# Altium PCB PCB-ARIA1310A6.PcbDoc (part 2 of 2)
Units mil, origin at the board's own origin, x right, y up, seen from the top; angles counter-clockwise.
Board outline 6000 x 4000 mil, 2 copper layers (Top Layer, Bottom Layer); 128 components, 134 nets, 554 pads, 227 vias.
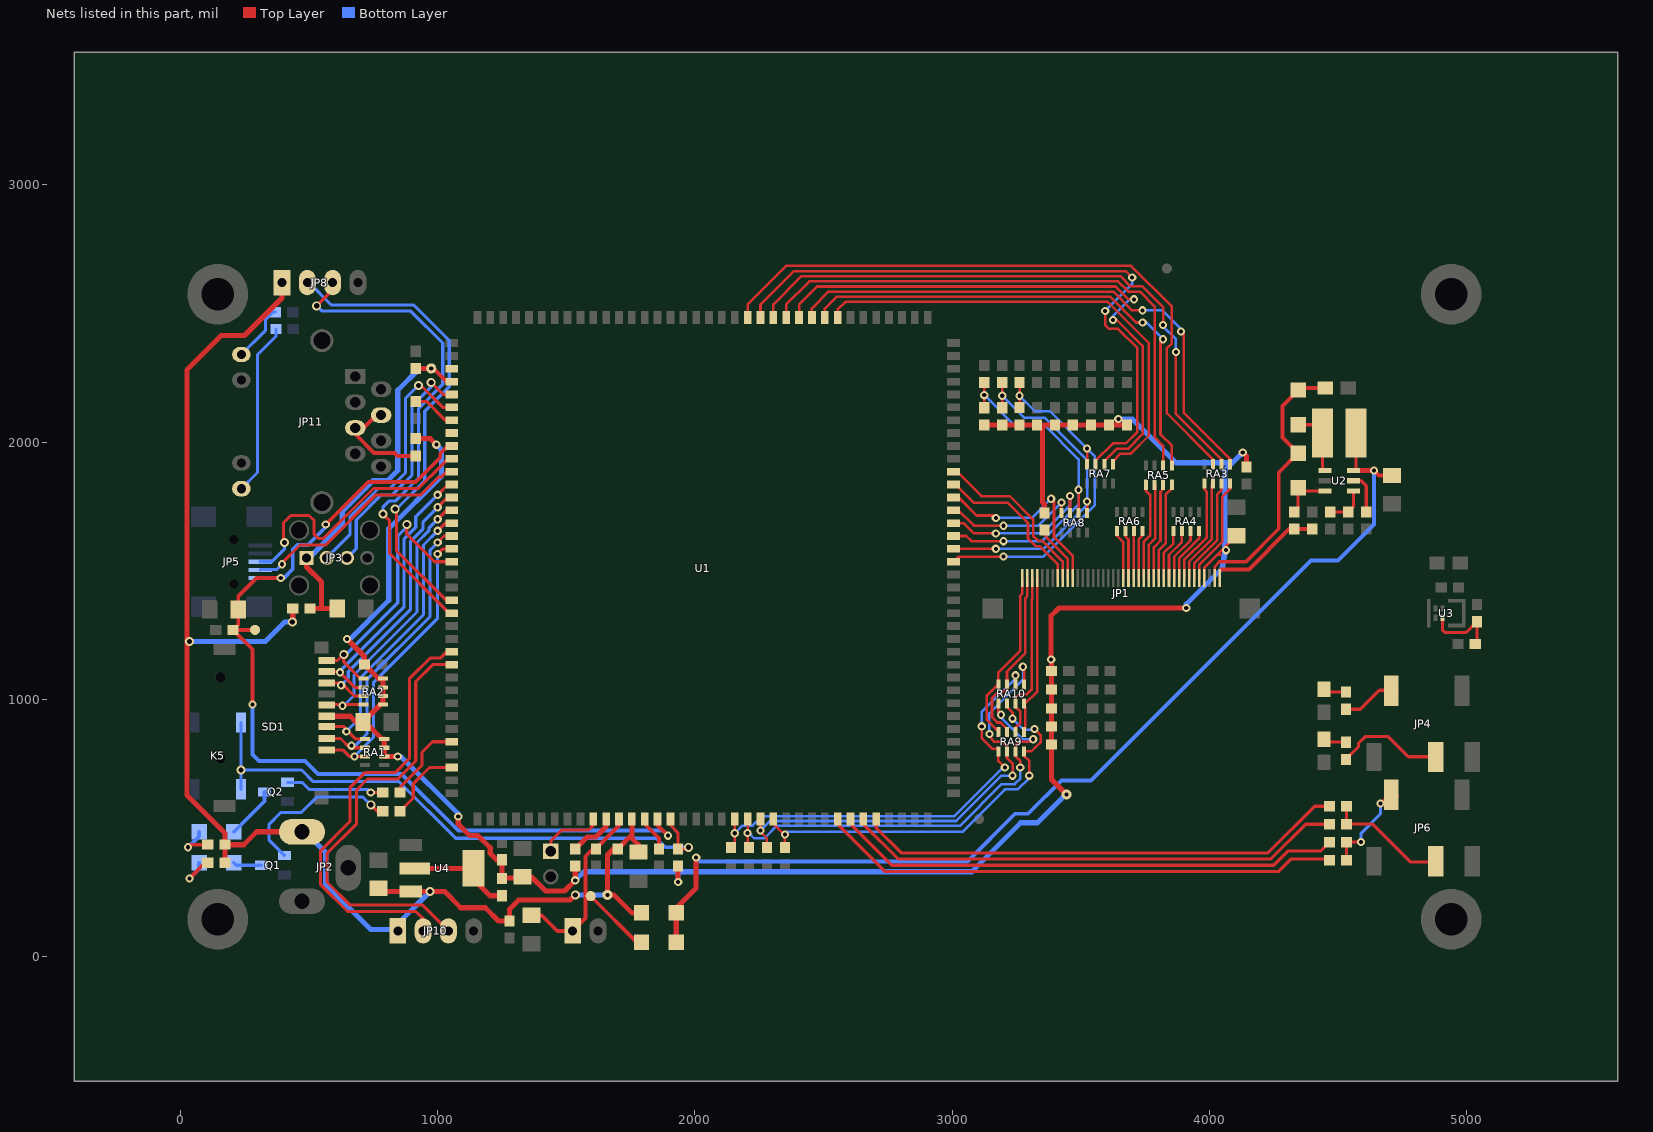
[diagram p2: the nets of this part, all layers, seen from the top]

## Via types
v1: diameter 32, hole 16, Top Layer to Bottom Layer, 208 vias
v2: diameter 35, hole 20, Top Layer to Bottom Layer, 19 vias

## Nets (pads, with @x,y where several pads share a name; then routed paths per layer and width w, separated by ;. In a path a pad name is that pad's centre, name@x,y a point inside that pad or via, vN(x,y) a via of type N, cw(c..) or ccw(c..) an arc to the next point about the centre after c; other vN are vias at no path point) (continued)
LCD_DATA11: R36.2 R47.1 RA7.5 U1.127 | length 1379.6
  Top Layer w10: U1.127@3005,1535 3025,1555 v1(3200,1555) ; R36.2@3262.48,2133.86 v1(3262.48,2180) R47.1@3262.48,2231.54 ; RA7.5@3524.8,1913.9 v1(3524.8,1975)
  Bottom Layer w10: v1(3200,1555) 3355,1555 3555,1755 3555,1944.8 v1(3524.8,1975) 3379.8,2120 3322.48,2120 v1(3262.48,2180)
LCD_DATA12: R35.2 R46.1 RA8.8 U1.128 | length 1342.4
  Top Layer w10: U1.128@3005,1585 v1(3170,1585) ; R35.2@3195,2133.46 v1(3195,2180) R46.1@3195,2231.54 ; v1(3524.8,1769.22) 3524.8,1724.29 RA8.8@3525.2,1723.9
  Bottom Layer w10: v1(3170,1585) 3355,1585 3524.8,1754.8 v1(3524.8,1769.22) 3524.8,1930.2 3360,2095 3280,2095 v1(3195,2180)
LCD_DATA13: R34.2 R45.1 RA8.7 U1.129 | length 1389.3
  Top Layer w10: U1.129@3005,1635 3055,1635 3075,1615 v1(3200,1615) ; R34.2@3125,2133.46 v1(3125,2182.5) R45.1@3125,2231.54 ; RA8.7@3491.73,1723.9 v1(3491.73,1815)
  Bottom Layer w10: v1(3125,2182.5) 3237.5,2070 3355,2070 3491.73,1933.27 3491.73,1756.93 3349.8,1615 v1(3200,1615)
LCD_DATA14: RA8.6 U1.130 | length 624.6
  Top Layer w10: U1.130@3010,1680 U1.130@3005,1685 3044.53,1685 3084.53,1645 v1(3170,1645) ; RA8.6@3458.27,1723.9 v1(3458.27,1790)
  Bottom Layer w10: v1(3170,1645) 3350,1645 3458.27,1753.27 v1(3458.27,1790)
LCD_DATA15: RA8.5 U1.131 | length 528
  Top Layer w10: U1.131@3005,1735 3025,1735 3085,1675 3195,1675 v1@3200,1670 ; RA8.5@3424.8,1723.9 3424.8,1765.28 v1(3425,1765.08)
  Bottom Layer w10: v1@3200,1670 3205,1675 3334.92,1675 v1(3425,1765.08)
  other v1: 3200,1675
LCD_DATA16: RA3.6 U1.15 | length 2521.7
  Top Layer w10: U1.15@2205,2485 2205,2535 2355,2685 3696.01,2685 3853.98,2527.04 3853.98,2383.98 3835,2365 3835,2112.2 4013.94,1933.27 RA3.6@4013.94,1913.9
LCD_DATA17: RA7.6 U1.14 | length 2497.4
  Top Layer w10: U1.14@2255,2485 2255,2535 2385,2665 3675,2665 v1(3700,2640) ; RA7.6@3558.27,1913.9 3558.27,1928.27 3625,1995 3675,1995 3720,2040 3720,2365.04 3645.04,2440 3610,2440 3595,2455 v1(3595,2510)
  Bottom Layer w10: v1(3595,2510) 3700,2615 v1(3700,2640)
LCD_DATA18: RA3.7 U1.13 | length 2365.6
  Top Layer w10: U1.13@2305,2485 2305,2535 2415,2645 3653.99,2645 3693.36,2605.63 3739.37,2605.63 3820,2525 v1(3820,2455) ; v1(3870,2350) 3870,2110 4047.4,1932.6 RA3.7@4047.4,1913.9
  Bottom Layer w10: v1(3820,2455) 3820,2450 3870,2400 v1(3870,2350)
LCD_DATA19: RA5.7 U1.12 | length 2192.4
  Top Layer w10: U1.12@2355,2485 2355,2535 2445,2625 3645,2625 3685,2585 3730,2585 3787.05,2527.95 3787.05,2018.96 3820.51,1985.5 RA5.7@3820.51,1908.9
LCD_DATA20: RA7.7 U1.11 | length 2233.1
  Top Layer w10: U1.11@2405,2485 2405,2535 2475,2605 3635.98,2605 3685.98,2555 v1(3707.4,2555) ; RA7.7@3591.73,1913.9 3591.73,1926.38 3640.35,1975 3685,1975 3740.87,2030.87 3740.87,2374.13 3640,2475 v1(3625,2475) ; v1@3709.4,2549.4 v1@3710,2550
  Bottom Layer w10: v1(3625,2475) 3625,2490 3690,2555 v1(3707.4,2555)
LCD_DATA21: RA3.8 U1.10 | length 2162.1
  Top Layer w10: U1.10@2455,2485 2455,2520 2520,2585 3627.4,2585 3700,2512.4 3739.8,2512.4 v1(3740,2512.2) ; v1(3890,2430.12) 3900,2420 3900,2115 4080.87,1934.13 RA3.8@4080.87,1913.9
  Bottom Layer w10: v1(3740,2512.2) 3817.8,2512.2 3890,2440 v1(3890,2430.12)
LCD_DATA22: RA5.8 U1.9 | length 1950.4
  Top Layer w10: U1.9@2505,2485 2505,2520 2550,2565 3615,2565 3715,2465 v1(3740.87,2465) ; v1(3820,2400) 3810,2390 3810,2030 3853.98,1986.02 RA5.8@3853.98,1908.9
  Bottom Layer w10: v1(3740.87,2465) 3755,2465 v1(3820,2400)
LCD_DATA23: RA7.8 U1.8 | length 1870.5
  Top Layer w10: U1.8@2555,2485 2555,2515 2585,2545 3605,2545 3764.41,2385.59 3764.41,2024.69 3694.72,1955 3655,1955 3625.2,1925.2 RA7.8@3625.2,1913.9
LCD_DISP: JP1.31 R27.1 | length 221.5
  Top Layer w10: R27.1@3365,1658.03 3365,1631.5 3449.45,1547.05 JP1.31@3449.45,1471.5
LCD_G0: JP1.13 RA5.1 | length 388.4
  Top Layer w10: JP1.13@3803.78,1471.5 3803.78,1580.28 3830,1606.5 3830,1796.5 3853.98,1820.47 RA5.1@3853.98,1839.1
LCD_G1: JP1.14 RA5.2 | length 382.7
  Top Layer w10: JP1.14@3784.09,1471.5 3784.09,1590.59 3810,1616.5 3810,1806.5 3820.51,1817.01 RA5.2@3820.51,1839.1
LCD_G2: JP1.15 RA5.3 | length 375.2
  Top Layer w10: JP1.15@3764.41,1471.5 3764.41,1600.91 3790,1626.5 RA5.3@3790,1836.14
LCD_G3: JP1.16 RA5.4 | length 379.9
  Top Layer w10: JP1.16@3744.72,1471.5 3744.72,1611.22 3770,1636.5 3770,1794.41 3753.58,1810.83 RA5.4@3753.58,1834.1
LCD_G4: JP1.17 RA6.1 | length 189.2
  Top Layer w10: JP1.17@3725.04,1471.5 3725.04,1621.54 3740.87,1637.36 RA6.1@3740.87,1654.1
LCD_G5: JP1.18 RA6.2 | length 183.4
  Top Layer w10: JP1.18@3705.35,1471.5 3705.35,1652.05 RA6.2@3707.4,1654.1
LCD_G6: JP1.19 RA6.3 | length 166.6
  Top Layer w10: 3673.94,1633.23 3685.67,1621.5 JP1.19@3685.67,1471.5
LCD_G7: JP1.20 RA6.4 | length 175.1
  Top Layer w10: RA6.4@3640.47,1636.03 3665.98,1610.51 JP1.20@3665.98,1471.5
LCD_HSYNC: JP1.32 U1.134 | length 678.4
  Top Layer w10: U1.134@3010,1880 U1.134@3005,1885 3019.1,1885 3114.1,1790 3224.1,1790 3315,1699.1 3315,1635.79 3334.18,1616.61 3349.89,1616.61 3429.76,1536.73 JP1.32@3429.76,1471.5
LCD_PCLK: JP1.30 U1.132 | length 787.4
  Top Layer w10: v1(3385,1780) 3396,1769 3396,1630.5 3469.13,1557.36 JP1.30@3469.13,1471.5
  Top Layer w12: U1.132@3005,1785 3025,1785 3095,1715 3160.2,1715 v1(3170,1705.2)
  Bottom Layer w10: v1(3170,1705.2) 3310.2,1705.2 v1(3385,1780)
LCD_R0: JP1.5 RA3.1 | length 417.1
  Top Layer w10: JP1.5@3961.26,1471.5 3961.26,1523.82 4050,1612.56 4050,1786.5 4080.87,1817.36 RA3.1@4080.87,1839.1
LCD_R1: JP1.6 RA3.2 | length 411.4
  Top Layer w10: JP1.6@3941.57,1471.5 3941.57,1529.59 4030,1618.02 4030,1796.5 4047.4,1813.9 RA3.2@4047.4,1839.1
LCD_R2: JP1.7 RA3.3 | length 405.7
  Top Layer w10: JP1.7@3921.89,1471.5 3921.89,1535.36 4010,1623.47 4010,1835.16 RA3.3@4013.94,1839.1
LCD_R3: JP1.8 RA3.4 | length 407.9
  Top Layer w10: JP1.8@3902.2,1471.5 3902.2,1541.13 3990,1628.93 3990,1806.5 3980.47,1816.03 RA3.4@3980.47,1839.1
LCD_R4: JP1.9 RA4.1 | length 214.8
  Top Layer w10: JP1.9@3882.52,1471.5 3882.52,1546.9 3960.2,1624.58 RA4.1@3960.2,1654.1
LCD_R5: JP1.10 RA4.2 | length 209.1
  Top Layer w10: JP1.10@3862.83,1471.5 3862.83,1554.33 3926.73,1618.23 RA4.2@3926.73,1654.1
LCD_R6: JP1.11 RA4.3 | length 203.4
  Top Layer w10: JP1.11@3843.15,1471.5 3843.15,1562.13 3893.27,1612.25 RA4.3@3893.27,1654.1
LCD_R7: JP1.12 RA4.4 | length 197.7
  Top Layer w10: JP1.12@3823.46,1471.5 3823.46,1569.96 3859.8,1606.3 RA4.4@3859.8,1654.1
LCD_VSYNC: JP1.33 U1.133 | length 640.1
  Top Layer w10: U1.133@3022.6,1835 U1.133@3005,1835 3013.38,1835 3083.31,1765.08 3214.92,1765.08 3295,1685 3295,1625.79 3325.79,1595 3341.5,1595 3410.08,1526.42 JP1.33@3410.08,1471.5
LED1: R1.1 U1.70 | length 304.1
  Top Layer w12: R1.1@853.58,565 905,616.42 905,671.58 968.42,735 U1.70@1055,735
LED2: R2.1 U1.68 | length 324.9
  Top Layer w12: R2.1@853.58,637.5 853.58,658.58 939,744 939,794 980,835 U1.68@1055,835
LED_A: C1.1 D4.2 D5.2 JP1.2 | length 1083.1
  Top Layer w10: JP1.2@4020.31,1471.5 4020.31,1515.31 4040,1535
  Top Layer w15: 4040,1535 4142.01,1535 4270,1662.99 4270,1882.5 D5.2@4345,1957.5 4285,2017.5 4285,2140 4345,2200 D4.2@4345,2202.5 4352.5,2210 C1.1@4450,2210
LED_K: JP1.1 R52.2 R53.2 | length 455.4
  Top Layer w10: JP1.1@4040,1471.5 4040,1500 4045,1505
  Top Layer w15: 4045,1505 4153.62,1505 4310.16,1661.54 R52.2@4330,1661.54 R53.2@4400,1661.54
MIC_BIAS: R38.1 U1.103 | length 1943.9
  Top Layer w12: U1.103@2655,535 2655,515 2791,379 4239,379 4374.38,514.38 R38.1@4466.51,514.38
MIC_DET: R39.1 U1.102 | length 1984.8
  Top Layer w12: U1.102@2605,535 2610,530 2610,510 2765,355 4250,355 4305,410 4432.16,410 R39.1@4466.54,444.38
MIC_LP: C33.2 U1.101 | length 2031.2
  Top Layer w12: U1.101@2555,535 2555,515 2740,330 4268.46,330 4318.46,380 4460.91,380 C33.2@4466.54,374.38
MIC_RP: C34.2 U1.104 | length 1911.8
  Top Layer w12: U1.104@2705,535 2705,500 2802,403 4228,403 4409.38,584.38 C34.2@4466.51,584.38
MMC0_CD: RA2.4 SD1.9 U1.54 | length 1079.7
  Top Layer w12: SD1.9@568.74,1150.91 610.91,1150.91 v2(635,1175) 635,1145 699.8,1080.2 RA2.4@712.24,1080.2 ; v2(880,1680) 880,1642.57 987.57,1535 U1.54@1055,1535
  Bottom Layer w12: v2(635,1175) 645,1175 845,1375 845,1635 880,1670 v2(880,1680)
MMC0_CLKO: RA2.1 SD1.5 U1.50 | length 1087.5
  Top Layer w12: SD1.5@568.74,977.68 570.87,979.8 RA2.1@712.24,979.8 ; v1@1000.45,1699.55 1035.9,1735 U1.50@1055,1735
  Bottom Layer w12: v1@635,980 640,980 675,1015 675,1094.46 920,1339.46 920,1610 965.9,1655.9 965.9,1665 v1@1000.45,1699.55
  other v1: 630,975 1000,1700
MMC0_CMD: RA1.4 SD1.3 U1.51 | length 1164
  Top Layer w12: SD1.3@568.74,895 632.43,895 682.23,845.2 RA1.4@717.6,845.2 ; v1(1000,1655) 1030,1685 U1.51@1055,1685
  Bottom Layer w12: v1(645,875) 700,930 700,1084.46 945,1329.46 945,1600 v1(1000,1655)
MMC0_DAT0: RA2.2 SD1.7 U1.49 | length 1082.5
  Top Layer w12: SD1.7@568.74,1064.29 625,1064.29 676.02,1013.27 RA2.2@712.24,1013.27 ; v1(1000,1746.62) 1038.38,1785 U1.49@1055,1785
  Bottom Layer w12: v1(625,1055) 652.64,1082.64 652.64,1107.3 895,1349.66 895,1615 943.42,1663.42 943.42,1690.04 v1(1000,1746.62)
MMC0_DAT1: RA2.3 SD1.8 U1.48 | length 1087.7
  Top Layer w12: SD1.8@568.74,1107.6 617.4,1107.6 v1(620,1105) 678.27,1046.73 RA2.3@712.24,1046.73 ; v1(1000,1795) 1040,1835 U1.48@1055,1835
  Bottom Layer w12: v1(620,1105) 620,1109.46 870,1359.46 870,1624.1 915,1669.1 915,1710 v1(1000,1795)
MMC0_DAT2: RA1.2 SD1.1 U1.53 | length 1142.8
  Top Layer w12: SD1.1@568.74,802.48 632.52,802.48 656.73,778.27 v1(676.73,778.27) RA1.2@717.6,778.27 ; v1(1000,1565) 1020,1585 U1.53@1055,1585
  Bottom Layer w12: v1(676.73,778.27) 750,851.54 750,1065 1000,1315 v1(1000,1565)
MMC0_DAT3: RA1.3 SD1.2 U1.52 | length 1193.2
  Top Layer w12: SD1.2@542.24,847.76 SD1.2@568.74,847.76 622.24,847.76 658.27,811.73 RA1.3@717.6,811.73 ; v1(1000,1610) 1025,1635 U1.52@1055,1635
  Bottom Layer w12: v1(665,820) 680,820 725,865 725,1075.71 970,1320.71 970,1580 v1(1000,1610)
NetC15_2: C15.2 U2.5 | length 159.8
  Top Layer w12: U2.5@4560,1850 4590,1850 4610,1830 C15.2@4610,1728.46
NetC27_1: C27.1 R21.2 | length 89.8
  Top Layer w12: C27.1@4445.62,844.97 4457.16,833.43 R21.2@4530.62,833.43
NetC28_1: C28.1 R22.2 | length 89.8
  Top Layer w12: C28.1@4445.62,1039.97 4457.16,1028.43 R22.2@4530.62,1028.43
NetC33_1: C33.1 JP6.5 R39.2 | length 385.4
  Top Layer w12: C33.1@4533.46,374.38 R39.2@4533.46,444.38 4534.09,445 v1(4590,445) ; v1(4665.62,594.97) 4695.86,625.21 JP6.5@4730.39,625.21
  Bottom Layer w12: v1(4590,445) 4590,479.35 4665.62,554.97 v1(4665.62,594.97)
NetC34_1: C34.1 JP6.2 R38.2 | length 478
  Top Layer w12: R38.2@4533.43,510 4538.43,515 4635,515 4783.06,366.94 JP6.2@4878.02,366.94 ; R38.2@4533.43,514.38 C34.1@4533.43,584.38
NetC41_1: C41.1 D2.2 D3.2 L1.2 U2.6 | length 4063.3
  Top Layer w12: U2.6@4560,1890 4570,1900 L1.2@4570,2035
  Top Layer w15: v1(4640,1890) 4659.88,1870.12 C41.1@4710,1870.12
  Top Layer w20: D3.2@1927.5,55 D2.2@1927.5,170 1927.5,188.92 2005,266.42 v1(2005,385) ; U2.6@4560,1890 v1(4640,1890)
  Bottom Layer w15: v1(2005,385) 2020,370 3060,370 3245,555 3295,555 3425,685 3540,685 4395,1540 4500,1540 4640,1680 v1(4640,1890)
NetD4_1: D4.1 L1.1 U2.1 | length 257.6
  Top Layer w12: D4.1@4345,2067.5 4407.5,2067.5 L1.1@4440,2035 4440,1900 U2.1@4450,1890
NetD5_1: D5.1 R52.1 U2.3 | length 210.4
  Top Layer w11.81: R52.1@4330,1728.46 4345,1743.46 D5.1@4345,1822.5
  Top Layer w12: D5.1@4345,1822.5 4357.5,1810 U2.3@4450,1810
NetJP1_37: JP1.37 RA9.8 RA10.5 | length 617.8
  Top Layer w10: RA9.8@3280.2,882.4 3285,887.2 3285,970 3280.2,974.8 RA10.5@3280.2,980 ; RA10.5@3280.2,983.58 RA10.5@3280.2,980 ; JP1.37@3331.34,1471.5 3331.34,1031.14 RA10.5@3280.2,980
NetJP1_38: JP1.38 RA9.7 RA10.6 | length 648.3
  Top Layer w10: RA9.7@3246.73,882.4 3246.73,890 3265,908.27 3265,952.28 3246.73,970.55 RA10.6@3246.73,983.58 3246.73,1005 3261.73,1020 3290.98,1020 3308.82,1037.83 3308.82,1387.32 3311.65,1390.15 JP1.38@3311.65,1471.5
NetJP1_39: JP1.39 RA9.6 RA10.2 | length 698.3
  Top Layer w10: RA9.6@3213.27,872.4 3213.27,884.88 3188.15,910 3175.67,910 3155,930.67 3155,1004.72 3171.26,1020.98 3190,1020.98 3213.27,1044.25 RA10.2@3213.27,1058.39 3213.27,1108.27 3285,1180 3285,1393.5 3291.97,1400.47 JP1.39@3291.97,1471.5
NetJP1_40: JP1.40 RA9.5 RA10.1 | length 669.6
  Top Layer w10: RA9.5@3179.8,882.4 3172.6,882.4 3135,920 3135,1015 3178.39,1058.39 RA10.1@3179.8,1058.39 3179.8,1104.8 3265,1190 3265,1403.5 3272.28,1410.78 JP1.40@3272.28,1471.5
NetJP4_2: JP4.2 R21.1 | length 423.7
  Top Layer w12: R21.1@4530.62,766.51 4580.62,816.51 4580.62,829.97 4605.62,854.97 4695.62,854.97 4773.65,776.94 JP4.2@4877.51,776.94
NetJP4_5: JP4.5 R22.1 | length 229.8
  Top Layer w12: R22.1@4530.62,961.51 4587.16,961.51 4660.86,1035.21 JP4.5@4729.87,1035.21
NetJP11_4: JP11.4 JP11.5 R23.2 | length 414.9
  Top Layer w12: JP11.5@680,2055 JP11.5@711.85,2055 ; JP11.4@761.85,2105 JP11.4@780,2105
  Top Layer w15: JP11.5@680,2055 680,2030.65 753.15,1957.5 832.5,1957.5 843.46,1946.54 R23.2@915,1946.54 ; JP11.5@711.85,2055 JP11.4@761.85,2105
NetJP11_9: JP11.9 R25.1 | length 225.3
  Bottom Layer w12: JP11.9@237.09,2340.63 330,2433.54 330,2475 360,2505 R25.1@370,2505
NetJP11_12: JP11.12 R26.1 | length 676.7
  Bottom Layer w12: JP11.12@237.09,1819 300,1881.91 300,2340 371.54,2411.54 R26.1@371.54,2440
NetJP12_1: JP12.1 U1.82 | length 254.2
  Top Layer w12: JP12.1@1440,410 1440,449 1483,492 1586.88,492 1605,510.12 U1.82@1605,535
NetLD1_1: LD1.1 R5.2 | length 174.1
  Top Layer w15: v1(35,303.46) 96.54,365 R5.2@106.54,365
  Bottom Layer w15: v1(35,303.46) 72.5,340.96 LD1.1@72.5,365
NetLD1_2: LD1.2 Q1.3 | length 111.6
  Bottom Layer w12: LD1.2@207.5,365 217.5,355 Q1.3@315,355
NetLD2_1: LD2.1 R6.2 | length 158.3
  Top Layer w15: v1(30,425) 40,435 R6.2@106.54,435
  Bottom Layer w15: v1(30,425) 72.5,467.5 LD2.1@72.5,485
NetLD2_2: LD2.2 Q2.3 | length 204.3
  Bottom Layer w15: LD2.2@207.5,485 326.54,604.04 Q2.3@326.54,640
NetQ1_1: Q1.1 R1.2 | length 655.3
  Top Layer w12: v2(740,590) 765,565 R1.2@786.65,565
  Bottom Layer w12: Q1.1@405,392.5 345,452.5 345,515 390,560 470,560 530,620 710,620 v2(740,590)
NetQ2_1: Q2.1 R2.2 | length 386.7
  Top Layer w12: v1(740,637.5) R2.2@786.65,637.5
  Bottom Layer w12: Q2.1@416.54,677.5 472.5,677.5 500,650 727.5,650 v1(740,637.5)
NetR3_1: R3.1 R4.2 U3.2 | length 292.1
  Top Layer w12: U3.2@4906.85,1317.28 4906.85,1268.15 4915,1260 4998.46,1260 R4.2@5040,1301.54 5040,1221.54 R3.1@5033.46,1215
NetR17_2: R17.2 U1.86 | length 146.4
  Top Layer w15: U1.86@1805,535 1810,535 1805,530 1805,515 1860,460 R17.2@1860,418.46
NetR49_2: R49.2 R50.2 U2.4 | length 159.8
  Top Layer w12: R49.2@4470,1728.46 R50.2@4540,1728.46 4560,1748.46 U2.4@4560,1810
NetR51_1: R51.1 U4.2 U4.4 | length 407.8
  Top Layer w20: U4.2@911,343.03 U4.4@1139.1,343.03 1139.1,300.9 1203.46,236.54 R51.1@1250,236.54
NetR54_2: R54.2 U1.83 | length 185.8
  Top Layer w20: R54.2@1535,418.46 1581.54,465 1615,465 1655,505 U1.83@1655,535
PWR_BUTT: K5.1 K5.2 R20.2 U1.88 | length 2295.9
  Top Layer w12: U1.88@1905,535 1905,510 1935,480 R20.2@1935,418.46 1968.46,418.46 v2(1975,425)
  Bottom Layer w12: K5.2@235,650 v2(235,725) ; K5.1@235,910 v2(235,725) ; v2(1975,425) 1885,425 1850,460 1070,460 850,680 516.26,680 471.26,725 v2(235,725)
"TS_ XPUL": C11.1 RA9.1 RA10.7 U1.96 | length 1632.9
  Top Layer w10: U1.96@2305,535 2305,515 2350,470 v1(2350,475) C11.1@2350,423.46 C11.1@2350,408.46 ; RA10.7@3213.27,983.58 3213.27,970.12 3235,948.39 3235,930 v1@3240,925 ; RA9.1@3280.2,807.6 RA9.1@3280.2,797.6 ; v1(3300,703.23) 3300,760 3280.2,779.8 RA9.1@3280.2,797.6 ; v1(3320,885) 3345,860 3345,833.99 3327.01,816 3326,816 3307.6,797.6 RA9.1@3280.2,797.6
  Bottom Layer w10: v1(2350,475) 2360,485 3040,485 3205,650 3255,650 3300,695 v1(3300,703.23) ; v1(3235,925) 3279,881 3316,881 v1(3320,885)
TS_XNUR: C10.1 RA9.3 RA10.4 U1.95 | length 1793.3
  Top Layer w10: U1.95@2255,535 v1(2255,490) 2255,485 2280,460 C10.1@2280,423.46 C10.1@2280,408.46 ; v1(3145,865) 3145,855 3165,835 3195,835 3213.27,816.73 3213.27,771.61 3235,749.88 v1(3235,703.23) ; v1(3275,1126.61) 3280.2,1121.41 RA10.4@3280.2,1058.39
  Bottom Layer w10: v1(2255,490) 2292,527 3015.53,527 3191.76,703.23 v1(3235,703.23) ; v1@3145,880 3145,945.98 3275.73,1076.72 3275.73,1125.88 v1(3275,1126.61)
TS_YNLR: C8.1 RA9.4 RA10.3 U1.93 | length 1774.3
  Top Layer w10: C8.1@2140,408.46 2155,423.46 v1(2155,479.23) U1.93@2155,535 ; v1(3115,895) 3115,850 3157.4,807.6 3179.8,807.6 3179.8,760.2 v1(3205,735) ; v1@3245,1095 v1(3246.73,1093.27) RA10.3@3246.73,1058.39
  Bottom Layer w10: v1(2155,479.23) 2185,509.23 2224.23,509.23 2260,545 3008.07,545 3198.07,735 v1(3205,735) ; v1@3115,910 3115,950 3246.73,1081.73 v1(3246.73,1093.27)
TS_YPLL: C9.1 RA9.2 RA10.8 U1.94 | length 1726.7
  Top Layer w10: U1.94@2205,535 v1(2205,480) 2205,413.46 C9.1@2210,408.46 ; RA10.8@3179.8,983.58 3179.8,950.2 v1(3190,940) ; v1(3265,735) 3265,760 3246.73,778.27 RA9.2@3246.73,797.6 3246.73,821.73 3260,835 3301.85,835 3311.85,845 v1(3315,845)
  Bottom Layer w10: v1(2205,480) 2210,480 2230,460 2270,460 2319,509 3031.83,509 3192.83,670 3242.78,670 3265,692.22 v1(3265,735) ; v1(3190,940) 3190,928.99 3273.99,845 v1(3315,845)
UART0_RXD: JP8.3 U1.58 | length 1943.7
  Top Layer w12: v2(530,2530) 591.85,2591.85 JP8.3@591.85,2620 ; v2(787.05,1720) 813.19,1693.86 813.19,1566.81 1045,1335 U1.58@1055,1335
  Bottom Layer w12: v2(530,2530) 551,2509 896,2509 1020,2385 1020,2225 925.25,2130.25 925.25,1860.25 836.5,1771.5 811.5,1771.5 787.05,1747.05 v2(787.05,1720)
UART0_TXD: JP8.2 U1.57 | length 1846.8
  Top Layer w12: v2(835,1740) 840,1735 840,1577.91 1032.91,1385 U1.57@1055,1385
  Bottom Layer w12: JP8.2@496.71,2623.29 587,2533 617.48,2533 907,2533 1045,2395 1045,2215 950,2120 950,1850 840,1740 v2(835,1740)
UART1_RXD: JP10.3 U1.62 | length 1708.9
  Top Layer w12: JP10.3@1041.85,100 941.85,200 659.88,200 570,289.88 570,401.54 685,516.54 685,647.5 727.5,690 845,690 915,760 915,1069.29 980.71,1135 U1.62@1055,1135
UART1_TXD: JP10.2 U1.61 | length 1720.8
  Top Layer w12: JP10.2@943.42,100 943.42,146.58 914.88,175.12 649.41,175.12 545,279.53 545,411.89 660,526.89 660,657.86 717.14,715 835,715 890,770 890,1079.65 970.35,1160 1010,1160 1035,1185 U1.61@1055,1185
USB0_DM: JP5.2 U1.47 | length 904.2
  Top Layer w12: v1@392.54,1527.46 465.08,1600 565,1600 760,1795 935,1795 1005,1865 1015,1865 1035,1885 U1.47@1055,1885
  Bottom Layer w12: JP5.2@310.24,1503.5 311.73,1505 375,1505 v1(395,1525)
USB0_DP: JP5.3 U1.46 | length 1072.6
  Top Layer w12: v2@405,1620 400,1625 400,1685.62 429.34,1714.96 500.04,1714.96 520,1695 520,1641.38 536.38,1625 555.71,1625 750.46,1819.75 925.15,1819.75 1011.5,1906.09 1011.5,1906.5 1040,1935 U1.46@1055,1935
  Bottom Layer w12: JP5.3@310.24,1535 355,1535 405,1585 v2(405,1610)
USB0_VBUS: C37.1 C38.2 JP5.1 TP12.1 U1.45 U1.87 | length 3778.8
  Top Layer w12: U1.45@1040,1985 U1.45@1055,1985
  Top Layer w15: v1(280,980) 280,1194.5 C38.2@204.5,1270 ; TP12.1@290,1270 C38.2@204.5,1270 ; v1(390,1472.01) 295.51,1472.01 225.12,1401.62 C37.1@225.12,1350 225.12,1290.61 C38.2@204.5,1270 ; v1(565,1680) 730,1845 915,1845 1010,1940 1010,1955 U1.45@1040,1985 ; U1.87@1855,535 1855,510 v1(1895,470)
  Bottom Layer w15: v1(280,980) 280,785 305,760 485,760 535,710 860,710 1080,490 1875,490 v1(1895,470) ; JP5.1@310.24,1472.01 v1(390,1472.01) 402.01,1472.01 436.93,1506.93 436.93,1581.93 455,1600 495,1600 565,1670 v1(565,1680)
USB1_DM: JP3.2 U1.42 | length 1008.3
  Top Layer w12: v2@930,2220 935,2220 1020,2135 U1.42@1055,2135
  Bottom Layer w12: JP3.2@568.74,1550 660,1641.26 660,1710 769.84,1819.84 813.43,1819.84 875,1881.42 875,2170 v2(925,2220) v2@930,2220
USB1_DP: JP3.3 U1.41 | length 941.2
  Top Layer w12: v2(975,2231.54) 1021.54,2185 U1.41@1055,2185
  Bottom Layer w12: JP3.3@647.48,1550 683.48,1586 683.48,1697.26 781.22,1795 823.46,1795 900,1871.54 900,2140 975,2215 v2(975,2231.54)
USB1_DRVVBUS: U1.44
USB1_ID: R28.1 U1.43 | length 170.4
  Top Layer w12: R28.1@915,2158.46 956.54,2158.46 1030,2085 U1.43@1055,2085
USB1_OC: U1.39
USB1_VBUS: C19.1 C20.2 JP3.1 R24.2 TP13.1 U1.40 | length 1487.3
  Top Layer w15: TP13.1@983.46,2286.54 U1.40@1035,2235
  Top Layer w20: JP3.1@487.21,1550 JP3.1@490,1550 490,1515 549.05,1455.95 549.05,1355 ; R24.2@503.46,1352.72 C19.1@609.88,1352.72 ; C20.2@915,2286.54 TP13.1@970,2286.54 ; v1(975,2286.54) TP13.1@983.46,2286.54 ; U1.40@1035,2235 U1.40@1055,2235
  Bottom Layer w20: JP3.1@490,1550 500,1550 629.33,1679.33 629.33,1730 749.33,1850 805.12,1850 845,1889.88 845,2201.54 930,2286.54 v1(975,2286.54)
VBAT: C39.1 C40.2 D3.1 JP7.1 TP11.1 U1.84 | length 1002.4
  Top Layer w15: C39.1@1365,160.12 1404.88,160.12 1465,100 JP7.1@1525,100 ; JP7.1@1525,85 JP7.1@1525,100 ; C40.2@1610,418.46 1603.46,418.46 1574.81,389.81 1574.81,225 ; C40.2@1611.73,416.73 1705,510 U1.84@1705,535 ; D3.1@1792.5,55 1775,55 1605,225 1574.81,225 ; JP7.1@1525,100 1574.81,149.81 1574.81,225
VCC: C4.2 C5.1 C35.1 C36.2 D2.1 JP2.1 JP8.1 JP10.1 R5.1 R6.1 R24.1 TP3.1 U1.85 U4.3 | length 5776.3
  Top Layer w20: v2@34.5,1225 v2(35,1225) ; R5.1@173.46,365 R6.1@173.46,435 ; JP8.1@395,2620 395,2560 249,2414 159,2414 25,2280 25,628 173.46,479.54 R6.1@173.46,435 ; v2(435,1300) 436.54,1301.54 R24.1@436.54,1352.72 ; JP2.1@460,525 472.64,512.36 JP2.1@472.64,485 296.42,485 246.42,435 R6.1@173.46,435 ; C35.1@770,264.88 782.4,252.48 U4.3@895,252.48 v2(970,252.48) 1027.52,252.48 1090,190 1185,190 1236.54,138.46 C4.2@1280,138.46 1280,185 1315,220 1515,220 v2(1535,240) ; U1.85@1760.06,529.94 U1.85@1755,535 1755,473.46 ; C5.1@1780,406.65 1780,435.12 1755,460.12 1755,473.46 ; D2.1@1792.5,170 1755,170 1685,240 v1(1660,240) 1660,395 1683.46,418.46 C36.2@1700,418.46 1755,473.46
  Bottom Layer w20: v2@25,1225 v2(35,1225) 330,1225 405,1300 v2(435,1300) ; JP2.1@472.64,485 485,485 565,405 565,280 740,105 JP10.1@830,105 ; JP10.1@845,100 845,127.48 v2(970,252.48) ; v2(1535,240) v1(1660,240)
VDD: C2.1 C3.2 C6.1 C7.1 C12.1 C13.2 JP1.4 R7.1 R8.1 R9.1 R10.1 R11.1 R20.1 R23.1 R27.2 R29.1 R30.1 R31.1 R32.1 R33.1 R34.1 R35.1 R36.1 R37.1 R51.2 R54.1 RA1.5 RA1.6 RA1.7 RA2.5 RA2.6 RA2.7 RA2.8 SD1.4 TP4.1 | length 8732.3
  Top Layer w10: JP1.4@3980.94,1471.5 3980.94,1512.44 4030,1561.5 ; 4045,1561.5 4030,1561.5 ; C12.1@4105,1636.38 C12.1@4104.88,1636.38 ; C12.1@4116.54,1648.03 C12.1@4104.88,1636.38 ; 4030,1561.5 C12.1@4104.88,1636.38
  Top Layer w20: SD1.4@568.74,934.37 660.63,934.37 683.03,911.97 C6.1@709.88,911.97 ; v1(647.48,1235) 716.18,1166.3 C7.1@716.18,1135 770.98,1080.2 RA2.5@787.05,1080.2 RA2.6@787.05,1046.73 RA2.7@787.05,1013.27 787.05,989.13 C6.1@709.88,911.97 ; v1(845,778.27) RA1.7@792.4,778.27 RA1.6@792.4,811.73 RA1.5@792.4,845.2 784.8,845.2 718.03,911.97 C6.1@709.88,911.97 ; R23.1@915,2013.46 971.54,2013.46 v1(995,1990) ; v1(1080,545) 1080,515 1125,470 1157.41,470 1204.4,423.01 1204.4,400.6 1228.46,376.54 C3.2@1250,376.54 R51.2@1250,305 ; R54.1@1535,351.54 v1(1535,296.42) 1493.58,255 1420,255 1365.12,309.88 C2.1@1330,309.88 1325.12,305 R51.2@1250,305 ; v1(1935,290) R20.1@1935,351.54 ; R34.1@3125,2066.54 R35.1@3195,2066.54 R37.1@3330,2066.54 3359,2066.54 ; R27.2@3358.46,1724.96 3358.46,1758.45 3351,1765.92 3351,2058.54 3359,2066.54 ; v1(3445,630) 3386.54,688.46 R11.1@3386.54,825 R10.1@3386.54,895 R9.1@3386.54,965 R8.1@3386.54,1037.6 R7.1@3386.54,1110 3386.54,1153.46 v1(3385,1155) 3385,1324.8 3415.2,1355 v1(3910,1355) ; v1@3645,2088.7 3645,2066.54 ; R33.1@3680,2066.54 3645,2066.54 ; v1(4130,1960) 4145,1945 C13.2@4145,1903.46 ; R51.2@1250,305 1248.46,305 R51.2@1250,303.46 R51.2@1250,305 ; 3359,2066.54 R29.1@3400,2066.54 R30.1@3469.13,2066.54 R31.1@3540,2066.54 R32.1@3610,2066.54 3645,2066.54
  Bottom Layer w20: v1(647.48,1235) 660,1235 810,1385 810,1662.91 1015,1867.91 1015,1970 v1(995,1990) ; v1(845,778.27) 856.73,778.27 1080,555 v1(1080,545) ; v1(1535,296.42) 1568.58,330 1935,330 1935,325 ; v1(1935,290) 1935,325 ; v1@3443.31,631.69 3331.61,520 3266.73,520 3076.73,330 1945,330 1940,325 1935,325 ; v1(3646.3,2090) 3700,2090 3870,1920 4090,1920 ; v1(3910,1355) 3910,1370 4050,1510 4060,1570 4060,1890 4090,1920 ; v1(4130,1960) 4090,1920
  other v1: 4065,1580
pads on no net: JP1.35 JP4.1 JP5.4 JP5.MH1 JP5.MH2 JP6.1 JP11.7 JP11.8 RA1.1 RA1.8 SD1.B U1.1 U1.2 U1.3 U1.4 U1.5 U1.6 U1.7 U1.16 U1.17 U1.19 U1.20 U1.21 U1.22 U1.23 U1.24 U1.25 U1.26 U1.27 U1.28 U1.29 U1.30 U1.31 U1.32 U1.55 U1.56 U1.59 U1.60 U1.63 U1.65 U1.67 U1.71 U1.72 U1.73 U1.74 U1.75 U1.76 U1.77 U1.78 U1.79 U1.80 U1.81 U1.90 U1.91 U1.92 U1.97 U1.98 U1.99 U1.100 U1.109 U1.110 U1.111 U1.114 U1.136 U1.137 U1.138 U1.139 U1.140 U1.141 U1.142 U1.143 U1.144

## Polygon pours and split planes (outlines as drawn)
AUGND on Top Layer "Top Layer-No Net" (solid, remove dead copper, pour order 3): 4394.64,1232.88 4649.64,1490 5085,1490 5085,280 5080,285.04 4255,285.04 4255,944.07 4300,989.45 4292.22,997.29 4292.22,1129.6 4292.22,1134.28 4645,1490
DGND on Top Layer "Top Layer-No Net" (solid, remove dead copper, pour order 6): 0,2720 5085,2720 5085,0 0,0 0,2720
AUGND on Bottom Layer "Top Layer-No Net" (solid, remove dead copper, pour order 5): 4650,1490 5085,1490 5085,285 4255,285 4255,935 4315,995 4315,1145 4315,1155 4650,1490
DGND on Bottom Layer "Top Layer-No Net" (solid, remove dead copper, pour order 4): 5,2720 5085,2720 5085,0 5080,5 0,5 0,2720

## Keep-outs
Keep-Out Layer:
  lines w5: 0,0 0,2720 5085,2720 5085,2105 5085,315 5085,310 5085,0 4745,0 4745,135 2060,135 2060,0 0,0

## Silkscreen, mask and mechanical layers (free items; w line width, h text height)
Top Overlay:
  lines w8: 3351.81,936.37 3810,936.37 ; 3351.81,1077 3810,1077 ; 3356.81,866.8 3810,866.8 ; 3356.81,1007.91 3810,1007.91 ; 3351.81,1140 3351.81,1211 3810,1211 3810,1140 ; 3351.81,1140 3810,1140 ; 3351.81,1140 3351.81,795 3810,795 3810,1140
  lines w10: 3355,796 3355,575 3365,565 3440,565 ; 3515,1139 3515,577.19 3527.19,565 3605,565
  text "9" at 3410.08,2495 h30 r90
  text "7" at 3555,2490 h30 r90
  text "5" at 3695,2490 h30 r90
  text "11" at 3272.28,2485 h30 r90
  text "13" at 3135,2475 h30 r90
  text "UART0" at 410,2445 h60
  text "USB_HOST" at 15,1480 h30
  text "1" at 3415,1165 h30
  text "0" at 3575,1165 h30
  text "BOOT4" at 3660,1095 h30
  text "SPEAKER" at 4747.45,1039.13 h30
  text "BOOT3" at 3660,1030 h30
  text "BOOT2" at 3660,953.39 h30
  text "BOOT1" at 3660,890 h30
  text "BOOT0" at 3660,815 h30
  text "MIC" at 4765,655 h30
  text "+5V PWR" at 455,555 h30
Bottom Overlay:
  text "GND" at 745,2580 h30 r270
  text "VCC" at 310,2575 h30 r270
  text "TXD0" at 480,2445 h30 r270
  text "RXD0" at 580,2445 h30 r270
  text "ARIA1310A6" at 4725,1780 h50 r270
  text "ariaboard.com" at 4825,1695 h70 r270
  text "Aria Ext Board A6" at 4925,1615 h60 r270
  text "USB0" at 245,1260 h30
  text "PWR_BUTT" at 245,975 h30
  text "VCC" at 835,175 h30 r270
  text "BATTERY" at 1660,175 h30
  text "TXD1" at 915,170 h30 r270
  text "RXD1" at 1035,170 h30 r270
  text "GND" at 1125,170 h30 r270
